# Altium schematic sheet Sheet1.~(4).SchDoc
size A
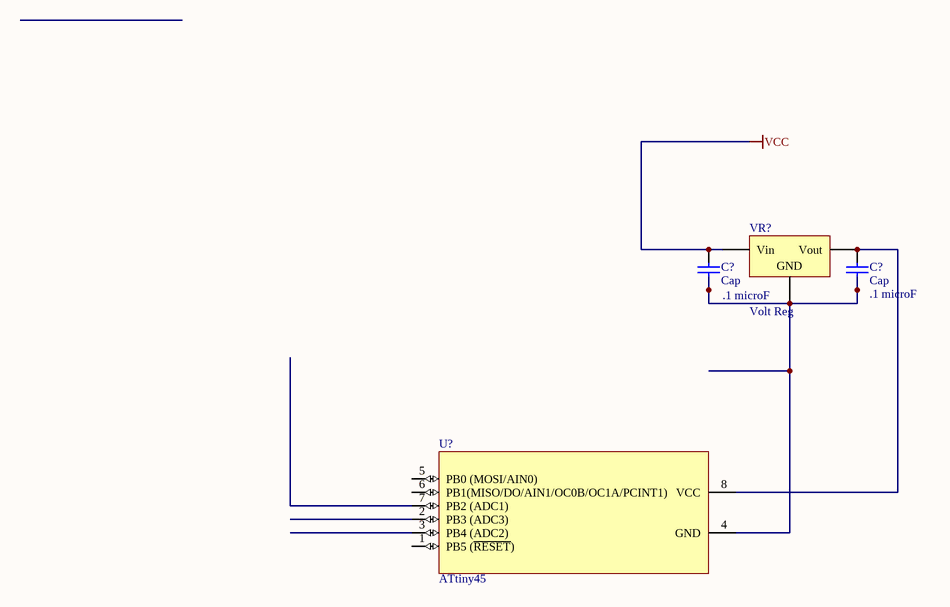
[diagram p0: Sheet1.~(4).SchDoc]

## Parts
(Parts that share a designator on the sheet are numbered #1, #2 ... from top to bottom, then left to right.)
C?#1  Cap  value .1 microF  [VP32-3.2]
C?#2  Cap  value .1 microF  [VP32-3.2]
U?  ATtiny45  [8S2_M]
VR?  Volt Reg  [SOT-23]

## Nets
VCC: C?#1.2 VR?.2(Vin)
NetC?#1_1: C?#1.1 C?#2.1 U?.4(GND) VR?.3(GND)
NetC?#2_2: C?#2.2 U?.8(VCC) VR?.1(Vout)

Not connected (* = marked no-connect by the designer): U? 1(PB5_(~{RESET})) 2(PB3_(ADC3)) 3(PB4_(ADC2)) 5(PB0_(MOSI/AIN0)) 6(PB1(MISO/DO/AIN1/OC0B/OC1A/PCINT1)) 7(PB2_(ADC1))

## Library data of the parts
C?#1 C?#2 = Cap: Capacitor
U? = ATtiny45: 8-Bit AVR Microcontroller with 1K Byte of Flash Memory
VR? = Volt Reg: Voltage Regulator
